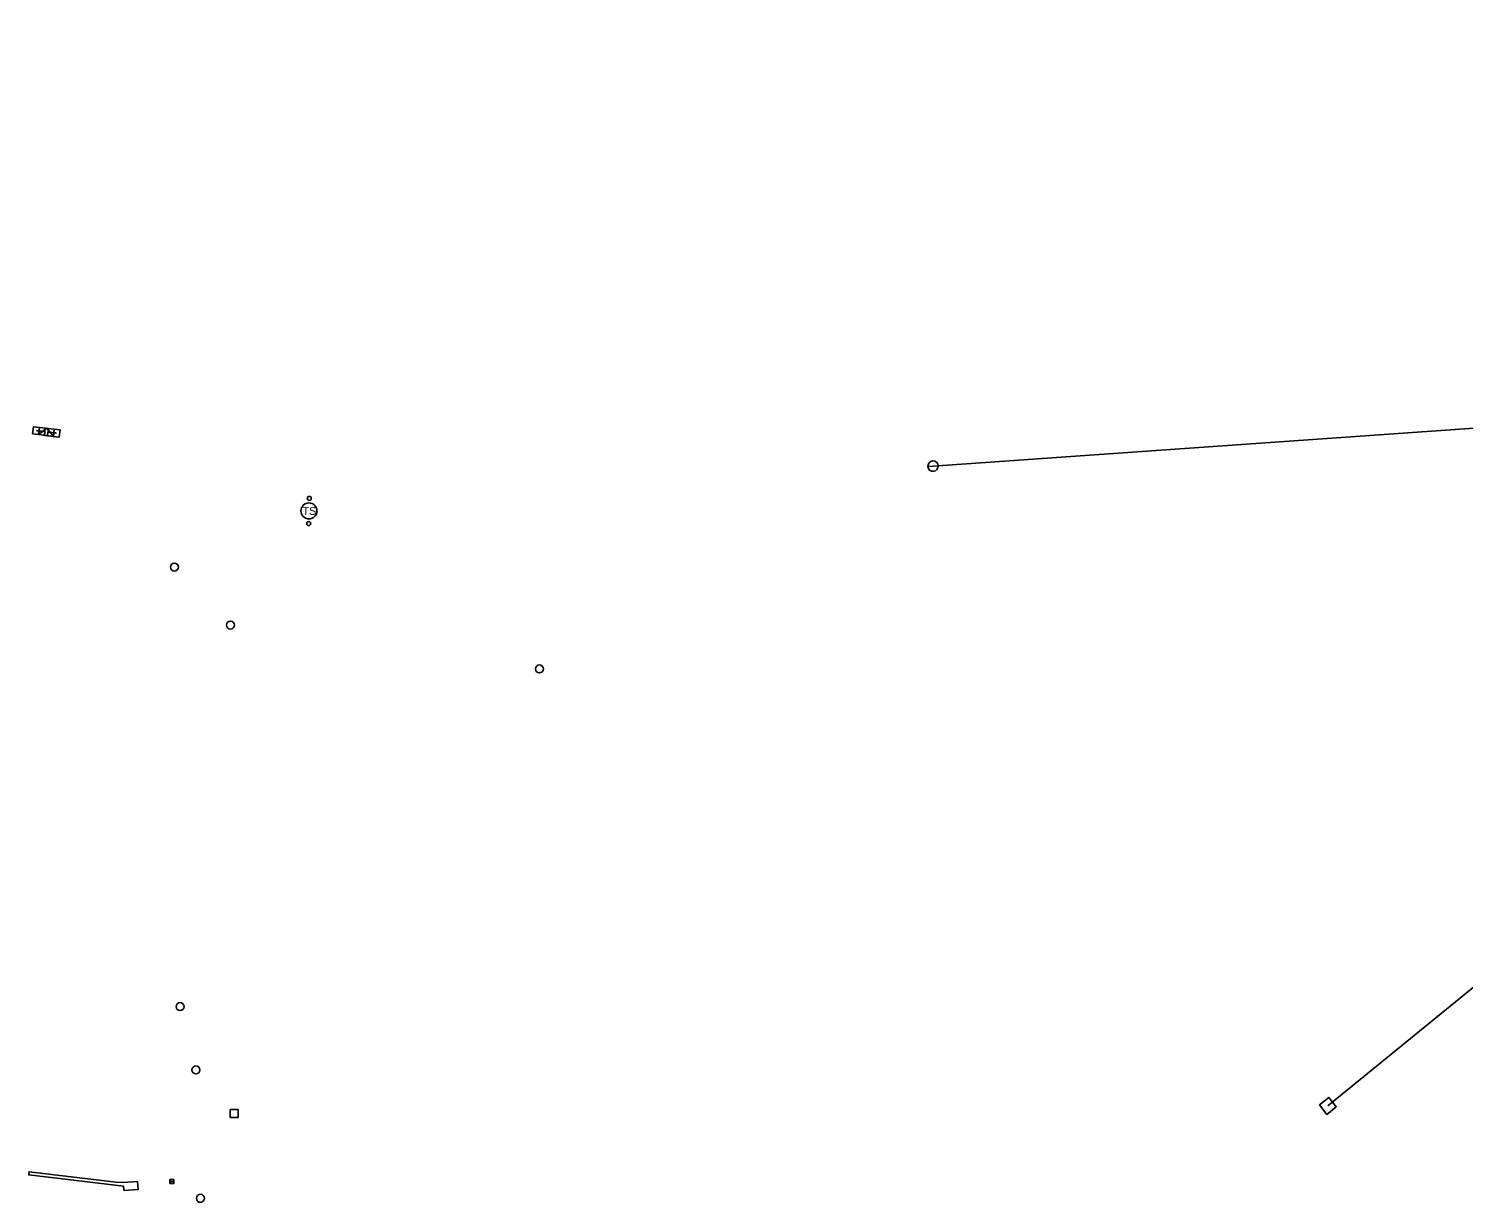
# Model space of a CAD drawing. Extents: x -545567 to -543527, y -1196984 to -1194464.
# Drawn here: x -545566.8 to -545387.5, y -1195078.1 to -1194931.3 of the extents above; entities that cross this region are included whole.
import ezdxf

# ---------------------------------------------------------------- set-up
doc = ezdxf.new("R2010")
doc.units = 0
for name, color, linetype in [('CIZÍ_NADZEM', 7, 'Continuous'), ('CIZÍ_PODZEM', 7, 'Continuous'), ('ELE_EON', 7, 'Continuous')]:
    doc.layers.add(name, color=color, linetype=linetype)

msp = doc.modelspace()

# ---------------------------------------------------------------- linework, layer by layer
at = {"layer": 'CIZÍ_NADZEM'}
for p, q in [((-545540.59, -1195066.47), (-545541.59, -1195066.47)), ((-545541.59, -1195066.47), (-545541.59, -1195067.47)), ((-545541.59, -1195067.47), (-545540.59, -1195067.47)), ((-545540.59, -1195067.47), (-545540.59, -1195066.47)), ((-545549.15, -1195075.49), (-545548.65, -1195075.49))]:
    msp.add_line(p, q, dxfattribs=at)
msp.add_lwpolyline([(-545549.15, -1195075.74), (-545548.65, -1195075.74), (-545548.65, -1195075.24), (-545549.15, -1195075.24)], close=True, dxfattribs=at)
for centre, radius in [((-545531.7, -1194990.07), 0.25), ((-545531.77, -1194993.22), 0.25), ((-545548.56, -1194998.66), 0.5), ((-545541.55, -1195005.91), 0.5), ((-545502.94, -1195011.4), 0.5), ((-545547.85, -1195053.62), 0.5), ((-545545.87, -1195061.53), 0.5), ((-545545.3, -1195077.59), 0.5)]:
    msp.add_circle(centre, radius, dxfattribs=at)
at = {"layer": 'CIZÍ_PODZEM'}
msp.add_lwpolyline([(-545554.87, -1195076.62), (-545553.09, -1195076.49), (-545553.16, -1195075.5), (-545554.96, -1195075.63), (-545555.87, -1195075.55), (-545566.73, -1195074.27), (-545566.77, -1195074.66), (-545554.9, -1195076.09), (-545554.87, -1195076.62)], dxfattribs=at)
at = {"layer": 'ELE_EON'}
msp.add_line((-545453.09, -1194985.99), (-545454.39, -1194986.09), dxfattribs=at)
for points in [[(-545404.4, -1195066.03), (-545290.02, -1194972.8), (-545252.36, -1194948.47), (-545238.74, -1194937.96), (-545230.3, -1194931.34)], [(-545565.54, -1194982.08), (-545564.5, -1194981.31), (-545563.68, -1194982.32)], [(-545381.37, -1194980.94), (-545453.74, -1194986.04)]]:
    msp.add_lwpolyline(points, dxfattribs=at)
for points in [[(-545566.28, -1194982), (-545564.42, -1194982.22), (-545564.31, -1194981.33), (-545566.17, -1194981.11)], [(-545565.76, -1194981.63), (-545564.83, -1194981.74), (-545564.83, -1194981.7), (-545565.76, -1194981.59)], [(-545565.43, -1194981.19), (-545563.57, -1194981.42), (-545563.68, -1194982.32), (-545565.54, -1194982.08)], [(-545564.81, -1194982.19), (-545562.95, -1194982.41), (-545562.84, -1194981.52), (-545564.7, -1194981.29)], [(-545564.29, -1194981.81), (-545563.36, -1194981.93), (-545563.36, -1194981.89), (-545564.29, -1194981.78)], [(-545404.51, -1195067.09), (-545403.34, -1195066.14), (-545404.29, -1195064.97), (-545405.46, -1195065.92)]]:
    msp.add_lwpolyline(points, close=True, dxfattribs=at)
msp.add_circle((-545531.74, -1194991.64), 1, dxfattribs=at)
for start, end in [(4.03, 184.03), (184.03, 4.03)]:
    msp.add_arc((-545453.74, -1194986.04), 0.65, start, end, dxfattribs=at)

# ---------------------------------------------------------------- texts
msp.add_text('TS', height=1, dxfattribs=at).set_placement((-545532.53, -1194992.14))

doc.saveas('drawing.dxf')
